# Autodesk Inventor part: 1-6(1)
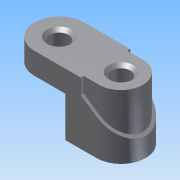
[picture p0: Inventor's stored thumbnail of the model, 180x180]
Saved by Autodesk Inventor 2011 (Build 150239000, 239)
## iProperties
Created: 2014-02
Part Number: 1-6(1)
Document SubType Name: Modeling
Designer: Administrator
Density: 1 g/cm^3
Author: Administrator
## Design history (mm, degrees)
sketch "草图1"
  geometry: L1 (-10, 8)-(10, 8); L2 (10, 8)-(10, -8); L3 (10, -8)-(-10, -8); L4 (-10, -8)-(-10, 8); L5 (0, 8)-(0, -8); A1 r 8 centre (10, 0) between (10, -8) and (10, 8); A2 r 8 centre (-10, 0) between (-10, 8) and (-10, -8); 2 further points
  constraints: 10 end point, 4 midpoint, 4 point on circle, 2 centre point, 2 parallel, 1 coincident, 1 horizontal, 1 horizontal alignment, 1 perpendicular, 1 vertical alignment
  dimensions: "d0" = 16 distance of L1.end L2.end; "d1" = 20 distance of L2.end L3.end
extrude "拉伸8" new body sketch "草图1" distance "d21" = 7; taper "d22" = 0 deg
extrude "拉伸9" join sketch "草图1" distance "d23" = 20; taper "d24" = 0 deg
hole "Hole1" diameter "d27" = 6; stored, may be unused: countersink angle "d31" = 90 deg, drill point angle "d33" = 118 deg; dims "d25" = 10, "d26" = 10, "d28" = 6, "d29" = 4, "d30" = 2, "d32" = 8
hole "Hole2" diameter "d36" = 6; stored, may be unused: countersink angle "d40" = 90 deg, drill point angle "d42" = 118 deg; dims "d34" = 10, "d35" = 10, "d37" = 6, "d38" = 4, "d39" = 2, "d41" = 8
hole "Hole3" diameter "d45" = 9; stored, may be unused: countersink angle "d49" = 90 deg, drill point angle "d51" = 0 deg; dims "d43" = 10, "d44" = 10, "d46" = 6, "d47" = 4, "d48" = 2, "d50" = 3
chamfer "倒角2" distance "d52" = 1; stored, may be unused: second distance "d53" = 2, angle "d54" = 45 deg
chamfer "倒角3" distance "d55" = 1; stored, may be unused: second distance "d56" = 2, angle "d57" = 45 deg
sketch "草图7"
  geometry: L1 (0, 7)-(20, 7) reference; L2 (15, 7)-(15, 2.055); L3 (15, 2.055)-(34.315, -11.126); 1 further point
  constraints: 4 end point, 1 perpendicular, 1 point on line
feature "分割1" sketch "草图7"
  node "实体2"
sketch "草图8"
  geometry: L1 (5, -8)-(5, 8) reference; L2 (5, -8)-(10, -8) reference; L3 (10, 8)-(5, 8) reference; L4 (10, 7.055)-(5, 7.055); L5 (10, -7.055)-(5, -7.055); A1 r 8 centre (10, 0) between (10, -8) and (10, 8) reference; A2 r 7.055 centre (10, 0) between (10, -7.055) and (10, 7.055); 1 further point
  constraints: 4 end point, 2 perpendicular, 2 point on circle, 2 point on line, 2 tangent, 1 centre point, 1 coincident
extrude "拉伸10" cut sketch "草图8" stored distance "d58" = 15; taper "d59" = 0 deg
feature "合并1"
  node "实体3"
node "实体4"
